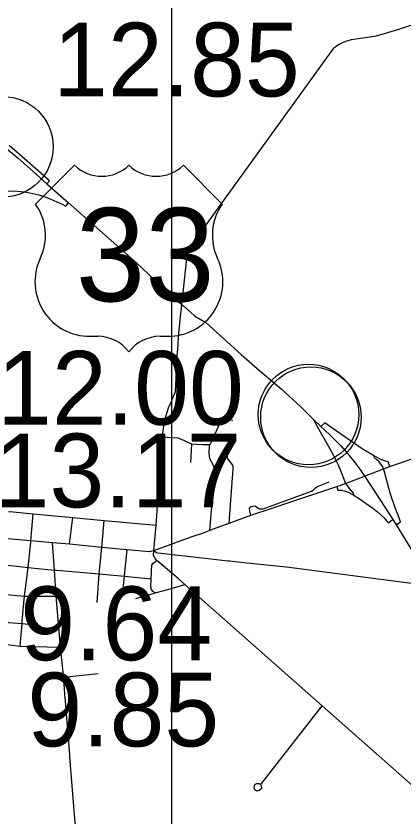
# Model space of a CAD drawing. Extents: x 1659811 to 1934326, y 644115 to 934867.
# Drawn here: x 1727270 to 1733046, y 811541 to 823471 of the extents above; entities that cross this region are included whole.
import ezdxf

# ---------------------------------------------------------------- set-up
doc = ezdxf.new("R2010")
doc.units = 0
for name, color, linetype in [('Default', 7, 'Continuous'), ('GM_X_City_Street', 7, 'Continuous'), ('GM_X_County_Road', 7, 'Continuous'), ('GM_X_Interchange_Ramps', 7, 'Continuous'), ('GM_X_Township_Road', 7, 'Continuous'), ('GM_X_US_Route', 7, 'Continuous'), ('GM_X_US_Shield', 7, 'Continuous'), ('SC_Scratch1', 7, 'Continuous')]:
    doc.layers.add(name, color=color, linetype=linetype)

msp = doc.modelspace()

# ---------------------------------------------------------------- linework, layer by layer
at = {"layer": 'Default'}
for centre in [(1727074, 821521), (1731636, 817527), (1731672, 817488)]:
    msp.add_circle(centre, 750, dxfattribs=at)
at = {"layer": 'GM_X_City_Street'}
for points in [[(1729733, 819065), (1729733, 819065), (1729744, 819170), (1729764, 819353), (1729822, 819851), (1729822, 819853)], [(1729684, 818485), (1729694, 818680), (1729730, 819039), (1729733, 819065)], [(1729361, 815878), (1729452, 817190), (1729453, 817196), (1729465, 817284), (1729487, 817434), (1729547, 817626), (1729586, 817710), (1729619, 817804), (1729650, 817864), (1729683, 818476), (1729684, 818485)], [(1730163, 815804), (1730238, 816673), (1730234, 816715), (1730219, 816770), (1730161, 816867), (1730154, 816951), (1730157, 817063), (1730167, 817083), (1730212, 817169), (1730214, 817173), (1730312, 817395), (1730333, 817421), (1730345, 817435), (1730369, 817445), (1730409, 817447), (1730507, 817444)], [(1729453, 817196), (1729686, 817178), (1729724, 817164), (1729844, 817110), (1729892, 817090), (1729896, 817090), (1730053, 817080), (1730167, 817083)], [(1729882, 816811), (1729896, 817090)], [(1730499, 816776), (1730490, 816793), (1730432, 816866), (1730426, 816906), (1730435, 816965), (1730450, 817109), (1730444, 817125), (1730420, 817146), (1730212, 817169)], [(1730451, 815910), (1730513, 816717), (1730511, 816753), (1730509, 816758), (1730499, 816776)], [(1730773, 816026), (1730758, 816089), (1730754, 816126), (1730771, 816150), (1730803, 816163), (1730841, 816165), (1730897, 816124), (1730939, 816120), (1730961, 816124), (1731678, 816387), (1731708, 816407), (1731740, 816436), (1731770, 816456), (1731944, 816525)], [(1731358, 816222), (1732057, 816455), (1732188, 816500)], [(1730118, 815785), (1730163, 815804), (1730451, 815910), (1730773, 816026), (1731109, 816138)], [(1731109, 816138), (1731358, 816222)], [(1727166, 816079), (1727180, 816080), (1727526, 816049), (1728118, 815991), (1728587, 815950), (1729361, 815878)], [(1727490, 815622), (1727492, 815644), (1727526, 816049)], [(1728070, 815595), (1728118, 815991)], [(1728514, 815153), (1728514, 815154), (1728549, 815545), (1728587, 815950)], [(1729325, 815501), (1729361, 815878)], [(1729325, 815501), (1729899, 815707), (1730068, 815765), (1730069, 815765)], [(1729325, 815501), (1729262, 815478), (1728929, 815509), (1728549, 815545), (1728070, 815595), (1727813, 815617), (1727492, 815644), (1727142, 815676), (1727131, 815677)], [(1727365, 814449), (1727399, 814819), (1727454, 815248), (1727490, 815622)], [(1727999, 813352), (1727992, 813444), (1727980, 813611), (1727978, 813638), (1727937, 814060), (1727872, 814821), (1727846, 815208), (1727813, 815617)], [(1728891, 815122), (1728929, 815509)], [(1742101, 804043), (1742093, 804050), (1742065, 804074), (1741320, 804731), (1739641, 806217), (1739434, 806407), (1738389, 807366), (1736980, 808653), (1733958, 811316), (1731839, 813182), (1729791, 814991), (1729692, 815084), (1729374, 815349), (1729340, 815392), (1729320, 815427), (1729325, 815501)], [(1729325, 815501), (1729369, 815472), (1729389, 815466), (1730093, 815386)], [(1726788, 815312), (1727105, 815284), (1727454, 815248), (1727846, 815208), (1727881, 815205)], [(1729347, 814870), (1729314, 814890), (1729294, 814918), (1729285, 814951), (1729288, 815078), (1729300, 815288), (1729318, 815310), (1729374, 815349)], [(1730714, 815318), (1731309, 815256), (1733248, 815002)], [(1727881, 815205), (1728514, 815154), (1728891, 815117), (1729288, 815078)], [(1728483, 814727), (1728514, 815153)], [(1728870, 814928), (1728891, 815117), (1728891, 815122)], [(1726007, 814953), (1726357, 814920), (1726711, 814886), (1727074, 814851), (1727399, 814819), (1727872, 814821)], [(1729319, 814861), (1729347, 814870), (1729537, 814921), (1729791, 814991)], [(1729058, 814786), (1729246, 814837), (1729319, 814861)], [(1727149, 814431), (1727163, 814429), (1727361, 814410), (1727632, 814384)], [(1727333, 814075), (1727361, 814410), (1727364, 814441), (1727365, 814449)], [(1726627, 814057), (1726629, 814058), (1726793, 814106), (1726827, 814116), (1726891, 814121), (1727021, 814115), (1727333, 814075), (1727937, 814060)], [(1727980, 813611), (1728498, 813664)], [(1728073, 812457), (1728024, 813068), (1728003, 813313), (1727999, 813352)], [(1730926, 812005), (1730940, 811954), (1730919, 811934), (1730899, 811923), (1730865, 811911), (1730847, 811925), (1730831, 811941), (1730824, 811966), (1730828, 811992), (1730842, 812018), (1730864, 812025), (1730896, 812025), (1730912, 812015), (1730941, 812031), (1731839, 813182)], [(1729856, 807362), (1729812, 807825), (1729783, 808029), (1729694, 808221), (1729458, 808682), (1728490, 810325), (1728194, 811184), (1728183, 811253), (1728170, 811339), (1728151, 811500), (1728076, 812421), (1728073, 812457)]]:
    msp.add_lwpolyline(points, dxfattribs=at)
at = {"layer": 'GM_X_County_Road'}
for points in [[(1732031, 823005), (1732054, 823025), (1732105, 823055), (1732195, 823096), (1732277, 823118), (1732652, 823176), (1732971, 823271), (1737518, 824773), (1737574, 824824), (1737615, 824876), (1737646, 824928), (1737669, 825023), (1737667, 825165), (1737638, 825442), (1737584, 825976)], [(1729924, 820093), (1729954, 820144), (1732013, 822989), (1732031, 823005)], [(1729822, 819853), (1729828, 819899), (1729852, 819973), (1729924, 820093)], [(1730069, 815765), (1730118, 815785)]]:
    msp.add_lwpolyline(points, dxfattribs=at)
at = {"layer": 'GM_X_Interchange_Ramps'}
for points in [[(1727732, 820969), (1727771, 821015), (1727478, 821273), (1727170, 821538)], [(1726538, 820828), (1726569, 820830), (1726742, 820839), (1727003, 820858), (1727176, 820864), (1727294, 820859), (1727390, 820850), (1727479, 820832), (1727610, 820804), (1727699, 820776), (1727790, 820741), (1727881, 820702), (1727957, 820664), (1728012, 820636), (1728055, 820687)], [(1732850, 816751), (1732826, 816821), (1732783, 816832), (1732717, 816857), (1732651, 816891), (1732622, 816905), (1732437, 817014), (1732197, 817182), (1731985, 817331), (1731881, 817403), (1731821, 817347)], [(1732757, 816718), (1732741, 816753), (1732717, 816787), (1732688, 816820), (1732656, 816854), (1732613, 816890), (1732622, 816905)], [(1732944, 815882), (1733011, 815927), (1732973, 816025), (1732932, 816124), (1732853, 816354), (1732772, 816674), (1732757, 816718)], [(1732188, 816500), (1732212, 816470), (1732239, 816430), (1732266, 816397), (1732300, 816357), (1732311, 816345), (1732301, 816330)], [(1732057, 816455), (1732071, 816398), (1732083, 816402), (1732130, 816400), (1732188, 816387), (1732240, 816363), (1732274, 816346), (1732301, 816330), (1732396, 816272), (1732598, 816132), (1732658, 816082), (1732709, 816037), (1732765, 815986), (1732823, 815914), (1732894, 815962)]]:
    msp.add_lwpolyline(points, dxfattribs=at)
at = {"layer": 'GM_X_Township_Road'}
for points in [[(1730093, 815386), (1730430, 815348), (1730455, 815345)], [(1730455, 815345), (1730714, 815318)]]:
    msp.add_lwpolyline(points, dxfattribs=at)
at = {"layer": 'GM_X_US_Route'}
for points in [[(1724808, 822326), (1725002, 822321), (1725211, 822292), (1725437, 822254), (1725759, 822183), (1726008, 822099), (1726222, 822024), (1726442, 821929), (1726697, 821786), (1726893, 821660), (1727092, 821523), (1727302, 821350), (1727525, 821154), (1727732, 820969), (1728055, 820687), (1729076, 819787), (1729501, 819384), (1729744, 819170), (1729778, 819140), (1729931, 819004)], [(1729931, 819004), (1729934, 819001), (1730105, 818901), (1730630, 818423), (1730910, 818181), (1731227, 817910), (1731348, 817800)], [(1731348, 817800), (1731519, 817645), (1731705, 817461), (1731821, 817347), (1731950, 817231), (1732111, 817066), (1732223, 816943), (1732329, 816813), (1732415, 816695), (1732441, 816655)], [(1731705, 817461), (1731812, 817269), (1731905, 817107), (1732005, 816929), (1732076, 816777), (1732143, 816621), (1732165, 816562)], [(1732599, 816658), (1732757, 816718), (1732850, 816751), (1733451, 816963), (1733500, 816982)], [(1732165, 816562), (1732188, 816500), (1732471, 816608), (1732599, 816658)], [(1732441, 816655), (1732471, 816608), (1732475, 816603), (1732710, 816244), (1732894, 815962), (1732927, 815909)], [(1732927, 815909), (1732944, 815882), (1733412, 815120), (1733522, 814933)]]:
    msp.add_lwpolyline(points, dxfattribs=at)
at = {"layer": 'GM_X_US_Shield'}
for p, q in [((1728143, 821247), (1727563, 820667)), ((1730348, 820667), (1729768, 821247)), ((1728375, 818695), (1728491, 818695)), ((1729420, 818695), (1729536, 818695))]:
    msp.add_line(p, q, dxfattribs=at)
for centre, radius, start, end in [((1728550, 821661), 580, 225.573, 314.427), ((1729362, 821661), 580, 225.573, 314.427), ((1726898, 820201), 812, 334.5471, 35.0009), ((1731013, 820201), 812, 144.9991, 205.4529), ((1728366, 819507), 812, 154.8319, 270.6383), ((1729545, 819507), 812, 269.3617, 25.1681), ((1728491, 818114), 580, 36.8699, 90), ((1729420, 818114), 580, 90, 143.1301)]:
    msp.add_arc(centre, radius, start, end, dxfattribs=at)
at = {"layer": 'SC_Scratch1'}
msp.add_lwpolyline([(1729596, 899996), (1925846, 899996), (1925846, 765496), (1729596, 765496)], close=True, dxfattribs=at)

# ---------------------------------------------------------------- texts
at = {"layer": 'Default'}
for s, p in [('12.85', (1727824, 822271)), ('12.00', (1726989, 817375)), ('13.17', (1726952, 816144)), ('9.64', (1727334, 813864)), ('9.85', (1727440, 812579))]:
    msp.add_text(s, height=1100, dxfattribs=at).set_placement(p)
at = {"layer": 'GM_X_US_Shield'}
msp.add_text('33', height=1392.2, dxfattribs=at).set_placement((1728163, 819217))

doc.saveas('drawing.dxf')
